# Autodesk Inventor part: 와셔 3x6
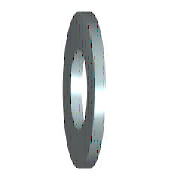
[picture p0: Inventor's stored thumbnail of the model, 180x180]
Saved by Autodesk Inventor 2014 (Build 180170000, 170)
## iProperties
IsCustomPart: 0
Created: 2012-02
Part Number: 와셔 3x6
Material: 강철, 연강
Description: 평면 와셔
Document SubType Name: Modeling
Standard: KS B 1326
Designer: mduedu
Standards Organization: KS
Language: ko-KR
Size Designation: 3x6
Categories: <MemberInstance><Categories><Category DisplayName="조임쇠" InternalName="e4da775c-781d-43d5-af7c-5136215cf5a6" Mnemonic="FSTN"><Category DisplayName="와셔" InternalN
Density: 7.86 g/cm^3
Mass: 0.0795112 g
Surface Area: 0.54915 cm^2
Volume: 0.0101159 cm^3
Appearance: Blue - Wall Paint - Glossy
Author: mduedu
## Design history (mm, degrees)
sketch "스케치"
  geometry: C1 r 3 at (0, 0); C2 r 1.6 at (0, 0); 1 further point
  constraints: 2 centre point, 2 coincident
  dimensions: "d0" = 3.2 diameter of C2 (= SD1); "d1" = 6 diameter of C1 (= SD2)
extrude "본체" new body sketch "스케치" distance "d2" = 0.5 (= SD); taper "d3" = 0 deg
workaxis "Work Axis1"
workplane "Work Plane1"
body "Solid1"
other parameters: "SD1" = 3.2 [user parameter; used in 1 equation term], "SD2" = 6 [user parameter; used in 1 equation term], "SD" = 0.5 [user parameter; used in 1 equation term], "d4" = 0, "d5" = 0, "d6" = 0, "d7" = 0, "NND" = 3 [user parameter]
